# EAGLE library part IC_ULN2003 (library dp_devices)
7 Darlington Array Driver
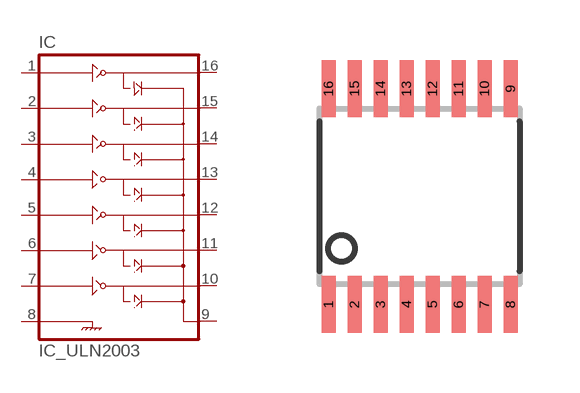
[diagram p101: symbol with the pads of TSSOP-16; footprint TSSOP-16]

Designator prefix IC

## IC_ULN2003-TSSOP-16  [TSSOP-16]
1  1B
2  2B
3  3B
4  4B
5  5B
6  6B
7  7B
8  GND
9  COM
10  7C
11  6C
12  5C
13  4C
14  3C
15  2C
16  1C

## Footprint TSSOP-16 (pad centres in mm)
smd 0.35 x 1.43: 1 -2.275,-2.7; 2 -1.625,-2.7; 3 -0.975,-2.7; 4 -0.325,-2.7; 5 0.325,-2.7; 6 0.975,-2.7; 7 1.625,-2.7; 8 2.275,-2.7; 9 2.275,2.7; 10 1.625,2.7; 11 0.975,2.7; 12 0.325,2.7; 13 -0.325,2.7; 14 -0.975,2.7; 15 -1.625,2.7; 16 -2.275,2.7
